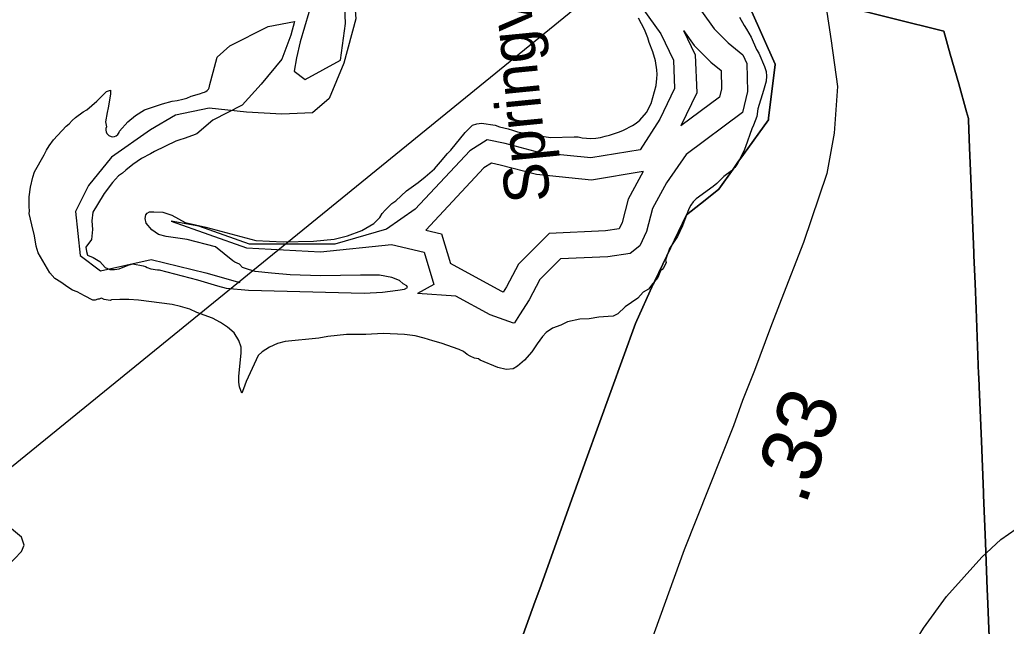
# Model space of a CAD drawing. Extents: x 1662474 to 1856135, y 779280 to 917889.
# Drawn here: x 1715736 to 1717827, y 818196 to 819482 of the extents above; entities that cross this region are included whole.
import ezdxf

# ---------------------------------------------------------------- set-up
doc = ezdxf.new("R2010")
doc.units = 0
for name, color, linetype in [('Exist Boundary Political City Limit New', 7, 'Continuous'), ('Exist Hydrographic Buffer Line', 7, 'Continuous'), ('Exist Hydrographic Creek Single Shore', 7, 'Continuous'), ('Exist Hydrographic Island Shore', 7, 'Continuous'), ('Exist Hydrographic Lake Shore', 7, 'Continuous'), ('Exist Hydrographic Misc Water Feature', 7, 'Continuous'), ('Exist Road Non-System Type 51', 7, 'Continuous'), ('Exist Road Secondary Mileage Tenths English Label', 7, 'Continuous'), ('Exist Road Secondary Structure Standard Bridge Number Label', 7, 'Continuous'), ('Exist Road Secondary Type 51 Attributed', 7, 'Continuous'), ('Exist Road Secondary Type 51 Label', 7, 'Continuous'), ('Map Preparation Boundary City Limit Buffer Line', 7, 'Continuous')]:
    doc.layers.add(name, color=color, linetype=linetype)

msp = doc.modelspace()

# ---------------------------------------------------------------- linework, layer by layer
at = {"layer": 'Exist Boundary Political City Limit New'}
for points in [[(1717284.5, 819505.2), (1717337.2, 819388.2), (1717337.2, 819387.6), (1717323.1, 819273.5), (1717322.6, 819270.2), (1717269.8, 819196.2), (1717258.1, 819179.9), (1717247.6, 819165.2), (1717217.6, 819123), (1717188.5, 819099.9), (1717149, 819068.4)], [(1717149, 819068.4), (1717188.5, 819099.9), (1717217.6, 819123), (1717247.6, 819165.2), (1717258.1, 819179.9), (1717269.8, 819196.2), (1717322.6, 819270.2), (1717323.1, 819273.5), (1717337.2, 819387.6), (1717337.2, 819388.2), (1717284.5, 819505.2)], [(1717790.4, 818173.4), (1717786.9, 818260.4), (1717786.4, 818273.7), (1717782.4, 818373.8), (1717778.4, 818474.2), (1717778.1, 818479.4), (1717773.8, 818588.8), (1717769.2, 818703.4), (1717768.4, 818724.4), (1717768.1, 818730.4), (1717762.6, 818869.1), (1717760.4, 818923), (1717758, 818982.4), (1717757.9, 818987.8), (1717751.5, 819145.7), (1717749, 819210.5), (1717746.6, 819269), (1717746.4, 819273.1), (1717742.5, 819286.9), (1717725.9, 819346), (1717707.9, 819409.6), (1717694.1, 819458.1), (1717478.1, 819512)], [(1717478.1, 819512), (1717694.1, 819458.1), (1717707.9, 819409.6), (1717725.9, 819346), (1717742.5, 819286.9), (1717746.4, 819273.1), (1717746.6, 819269), (1717749, 819210.5), (1717751.5, 819145.7), (1717757.9, 818987.8), (1717758, 818982.4), (1717760.4, 818923), (1717762.6, 818869.1), (1717768.1, 818730.4), (1717768.4, 818724.4), (1717769.2, 818703.4), (1717773.8, 818588.8), (1717778.1, 818479.4), (1717778.4, 818474.2), (1717782.4, 818373.8), (1717786.4, 818273.7), (1717786.9, 818260.4), (1717790.4, 818173.4)], [(1717149, 819068.4), (1717082.1, 818928.8), (1717081.8, 818927.9), (1717080.5, 818925), (1717078.6, 818921.1), (1717040.9, 818837.8), (1716936.5, 818549.8), (1716902.8, 818455.8), (1716869, 818362.1), (1716838, 818275.6), (1716828.5, 818249.1), (1716803, 818178.1)], [(1716803, 818178.1), (1716828.5, 818249.1), (1716838, 818275.6), (1716869, 818362.1), (1716902.8, 818455.8), (1716936.5, 818549.8), (1717040.9, 818837.8), (1717078.6, 818921.1), (1717080.5, 818925), (1717081.8, 818927.9), (1717082.1, 818928.8), (1717149, 819068.4)]]:
    msp.add_lwpolyline(points, dxfattribs=at)
at = {"layer": 'Exist Hydrographic Buffer Line'}
for points in [[(1717039.9, 819528.5), (1717094.3, 819452.3), (1717121.1, 819396.3), (1717123.8, 819336.6), (1717092.5, 819271.7), (1717050.9, 819206.6), (1716945.9, 819189.1), (1716839.2, 819200.2), (1716764.4, 819219.5), (1716726.6, 819227.4), (1716689.8, 819204.4), (1716574.1, 819080.2), (1716513, 819037.9), (1716403.8, 819006), (1716222.6, 819006), (1716115.4, 819044.6), (1716057.1, 819054.8), (1716216.9, 818998.4), (1716373.6, 818990.3), (1716523.5, 819005.9), (1716592.9, 818989.1), (1716613.4, 818920.8), (1716578.8, 818901.6)], [(1717180.8, 819500.4), (1717207.4, 819463.2), (1717237.5, 819433.1), (1717268.2, 819407.8), (1717276.7, 819389.6), (1717278.5, 819330.1), (1717267.8, 819285.7), (1717148.3, 819196.7), (1717106.8, 819136.7), (1717077, 819081.7), (1717064.3, 819033), (1717050.2, 819003.1), (1717029.8, 818986.5), (1716982.3, 818979.7), (1716881.7, 818975.1), (1716838, 818931.3), (1716815.4, 818888.4), (1716795.2, 818856.1), (1716784.8, 818839.2), (1716782.3, 818838.4), (1716733.1, 818856.4), (1716660.3, 818896.1), (1716578.8, 818901.6)], [(1717142.7, 819459.2), (1717165.3, 819427.6), (1717200.4, 819392.4), (1717222.2, 819374.5), (1717223.3, 819335.8), (1717219, 819317.9), (1717137.2, 819257)], [(1717142.7, 819459.2), (1717167.3, 819407.8), (1717170.9, 819327), (1717137.2, 819257)], [(1717057.1, 819160.3), (1716947.4, 819142), (1716830.9, 819154.2), (1716753.9, 819174), (1716735.4, 819177.8), (1716719.8, 819168.1), (1716596.8, 819036.1)], [(1717057.1, 819160.3), (1717025.5, 819102), (1717012.4, 819051.9), (1717006.2, 819038.7), (1716977.1, 819034.5), (1716857.9, 819029), (1716793.2, 818964.2), (1716767.7, 818915.8), (1716760.8, 818904.8), (1716755.9, 818906.6), (1716648.8, 818965)], [(1716596.8, 819036.1), (1716629.9, 819028.1), (1716648.8, 818965)]]:
    msp.add_lwpolyline(points, dxfattribs=at)
at = {"layer": 'Exist Hydrographic Creek Single Shore'}
msp.add_lwpolyline([(1715996.8, 820470.9), (1716158.5, 820299.6), (1716262.1, 820136.1), (1716307.5, 820029.2), (1716378.4, 819865.8), (1716435.4, 819651.8), (1716448.2, 819484.1), (1716422.5, 819389.9), (1716391.5, 819315.4), (1716356.1, 819284.6), (1716291.2, 819281.8), (1716216.8, 819286.5), (1716137.5, 819294.4), (1716066.4, 819279.9), (1716012.8, 819248.9), (1715930.4, 819190.9), (1715881.9, 819130.8), (1715854.2, 819075.8), (1715864, 818982.3), (1715907.5, 818949.8), (1716014.4, 818973.9), (1716130.6, 818945.8), (1716202.2, 818925.1)], dxfattribs=at)
at = {"layer": 'Exist Hydrographic Island Shore'}
msp.add_lwpolyline([(1716340.9, 819355.3), (1716415.7, 819396.7), (1716426.1, 819474.1), (1716420.9, 819618.7), (1716297, 819931.2), (1716263.5, 820075.8), (1716152.5, 820254), (1716054.4, 820334), (1716036.3, 820321.1), (1716033.8, 820274.6), (1716088, 820163.6), (1716134.4, 820055.1), (1716188.6, 819995.8), (1716229.9, 819938.9), (1716281.5, 819848.6), (1716307.3, 819771.1), (1716338.3, 819631.7), (1716348.6, 819497.4), (1716330.6, 819435.4), (1716322.8, 819401.8), (1716317.7, 819373.4)], close=True, dxfattribs=at)
at = {"layer": 'Exist Hydrographic Lake Shore'}
for points in [[(1716127.5, 819328.8), (1716130.6, 819330.1), (1716133.5, 819332.1), (1716135.9, 819335.1), (1716137.5, 819338.2), (1716138.2, 819341.6), (1716138.5, 819345.2), (1716146.2, 819370.8), (1716154.2, 819402.8), (1716180.9, 819426.8), (1716262.2, 819468.1), (1716318.2, 819478.8), (1716310.2, 819449.4), (1716291.6, 819398.8), (1716247.6, 819345.4), (1716207.5, 819301.4), (1716144.9, 819269.4), (1716111, 819240), (1716101.8, 819237.1), (1716084.2, 819230.3), (1716075, 819227.9), (1716066.6, 819224.6), (1716021.8, 819203), (1716012.8, 819197.8), (1715994.1, 819188.1), (1715975.5, 819175.2), (1715960.9, 819163.4), (1715953.5, 819156.8), (1715945.6, 819151.1), (1715932.5, 819137.1), (1715915.1, 819113.8), (1715900.5, 819090.7), (1715890.8, 819073.9), (1715888.9, 819056.1), (1715890.2, 819037.1), (1715888.1, 819015.9), (1715876, 819000.1), (1715877.4, 818990.4), (1715879.5, 818983.3), (1715891.8, 818978.1), (1715906, 818969.4), (1715917.2, 818957.1), (1715926.8, 818952.4), (1715936.6, 818952.4), (1715946.9, 818953.9), (1715965.5, 818961.6), (1715976, 818964.7), (1715997.9, 818960.5), (1716002.2, 818958.9), (1716005.8, 818956.6), (1716014.1, 818953.9), (1716028, 818951.6), (1716031.8, 818951.8), (1716112.8, 818930.8), (1716154.8, 818918), (1716173.4, 818913.2), (1716220.9, 818908.6), (1716465.8, 818902.2), (1716504.9, 818904.3), (1716537.2, 818908.6), (1716551.4, 818911.1), (1716557.4, 818914.3), (1716556.1, 818918), (1716548.8, 818922.2), (1716540.9, 818929), (1716524.4, 818935.6), (1716498.6, 818940.3), (1716458.2, 818940.3), (1716373.4, 818939.2), (1716309.1, 818941.3), (1716269.5, 818944.5), (1716235.1, 818948.2), (1716220.9, 818952.4), (1716207.8, 818957.1), (1716201.8, 818963.9), (1716191.8, 818968.4), (1716187.6, 818971), (1716150.9, 819000.4), (1716090.8, 819015.9), (1716046.6, 819022.2), (1716030.1, 819026.6), (1716016, 819036.9), (1716003.6, 819050.8), (1716001.8, 819060.8), (1716003.1, 819068.6), (1716006, 819072.1), (1716011.2, 819074.9), (1716020.4, 819075.2), (1716039.2, 819073.9), (1716058.5, 819067.6), (1716086.9, 819052.1), (1716130.1, 819042.1), (1716236.6, 819014.1), (1716294.4, 819011.4), (1716358.5, 819012.8), (1716402.2, 819017.2), (1716430.4, 819024), (1716461.1, 819035.6), (1716486.5, 819050), (1716499.1, 819062.6)], [(1716499.1, 819062.6), (1716504.1, 819071.5), (1716510.1, 819078.6), (1716524.6, 819092.2), (1716533.2, 819098.3), (1716555.6, 819119.3), (1716580.2, 819136.9), (1716595.2, 819149.2), (1716614.6, 819166.2), (1716627.8, 819180.7), (1716642.8, 819198.8), (1716649.8, 819205.6), (1716680, 819242.9), (1716695.5, 819258.9), (1716704.9, 819261.8), (1716714.4, 819262.9), (1716743.8, 819258.6), (1716752.6, 819255.2), (1716770.8, 819250.8), (1716780.5, 819248.2), (1716791, 819244.2), (1716811.8, 819240), (1716861.1, 819232.7), (1716910.6, 819234.2), (1716919.6, 819233.8), (1716928.2, 819231.9), (1716945.9, 819230.3), (1716957.1, 819231.1), (1716966.6, 819232.7), (1716976.9, 819235.6), (1716985.5, 819237.4), (1717007, 819244.5), (1717015.6, 819248.4), (1717034.2, 819258.1), (1717042.1, 819263.1), (1717049.8, 819269.1), (1717064.2, 819285.7), (1717073.9, 819304.9), (1717084.4, 819342.9), (1717086.2, 819357.6), (1717086.8, 819366.2), (1717086.2, 819375.7), (1717083.6, 819395.4), (1717077.6, 819414.1), (1717070.2, 819434.2), (1717067.1, 819444.2), (1717060.2, 819461.8), (1717047.1, 819485.7)], [(1717261.6, 819487.8), (1717271, 819470.2), (1717276.2, 819462.6), (1717286, 819445.2), (1717297, 819419.3), (1717302, 819411.1), (1717314.6, 819382.8), (1717317.5, 819372.3), (1717318.8, 819362.9), (1717317.8, 819352.1), (1717312.5, 819332.4), (1717300.5, 819293.1), (1717297.9, 819277), (1717291.2, 819258.6), (1717287.6, 819250.8), (1717274.2, 819212.8), (1717270.2, 819203.2), (1717256.9, 819177.6), (1717251.4, 819168.9), (1717244, 819161.6), (1717228, 819149.5), (1717213, 819134.8), (1717205.8, 819128.5), (1717169.8, 819102.2), (1717163.4, 819096.2), (1717157.9, 819088.8), (1717153.8, 819081.2), (1717140.4, 819045.2), (1717130.1, 819022.2), (1717113.2, 818997), (1717104.6, 818972.6), (1717105.8, 818967.6), (1717100.8, 818956.6), (1717097.5, 818952.4), (1717093.6, 818950), (1717087.9, 818935.6), (1717077.6, 818922.9), (1717068.4, 818911.1), (1717056.9, 818904.3), (1717045.6, 818892), (1717019.1, 818873.1), (1717003.4, 818858.4), (1716993.6, 818853.9), (1716983.1, 818852.9), (1716962.9, 818851.8), (1716942.5, 818848.2), (1716923, 818846.9), (1716896.8, 818841.3), (1716882.6, 818834.5), (1716864.8, 818828.2), (1716851.9, 818819.1), (1716844, 818810.1), (1716832.8, 818794.6), (1716821.1, 818777.6), (1716806, 818760.5), (1716791, 818747.4), (1716781.5, 818741.9), (1716766.6, 818740.8), (1716749.5, 818745), (1716711.8, 818760.5), (1716708.1, 818762.9), (1716699.9, 818764.7), (1716690.2, 818768.6), (1716684.5, 818772.1), (1716676.6, 818778.6), (1716667.1, 818783.1), (1716628.8, 818796.4), (1716611.2, 818801.2), (1716592.9, 818806.9), (1716574.2, 818811.9), (1716551.4, 818814.8)], [(1716551.4, 818814.8), (1716506.5, 818816.7), (1716469.5, 818814.8), (1716428.8, 818814.8), (1716389.1, 818810.1), (1716369.8, 818806.9), (1716298.6, 818800.1), (1716282.1, 818795.4), (1716265.2, 818787.8), (1716250.1, 818777.6), (1716241.1, 818769.9), (1716215.6, 818714.8), (1716210.4, 818699.1), (1716206.8, 818690.4), (1716201.8, 818703.8), (1716200.5, 818713.8), (1716200.5, 818726.1), (1716205.5, 818775.4), (1716205.5, 818787.8), (1716200.5, 818802.2), (1716190.5, 818818), (1716176, 818830.3), (1716161.1, 818840.3), (1716144.5, 818849.2), (1716111, 818861.6), (1716096.8, 818868.4), (1716076.6, 818874.1), (1716059, 818878.1), (1715987.6, 818887.8), (1715967.4, 818888.6), (1715948.2, 818888.6), (1715930.6, 818888.1), (1715927.5, 818887), (1715915.1, 818888.9), (1715910.8, 818891.2), (1715908.4, 818891.5), (1715904.6, 818889.4), (1715901.2, 818889.9), (1715895.8, 818887.8), (1715890.8, 818887.8), (1715872.9, 818896.4), (1715857.4, 818905.1), (1715847.5, 818908.6), (1715838.2, 818915.1), (1715823, 818925.9), (1715810.5, 818933.4), (1715800, 818945.6), (1715774.8, 818988.1), (1715771.1, 819001.9), (1715767.4, 819023.8), (1715761.6, 819047.4), (1715756.1, 819071.5), (1715756.9, 819076.2), (1715756.1, 819086.5), (1715755.9, 819106.7), (1715759, 819127.4), (1715763.5, 819148.7), (1715767.6, 819160), (1715787.9, 819195.7), (1715792.4, 819205.6), (1715798.4, 819215.1), (1715807.2, 819227.7), (1715834.4, 819256.8), (1715840.6, 819261.8), (1715846.9, 819268.4), (1715854.2, 819274.7), (1715870.2, 819287), (1715878.4, 819291.2), (1715899.1, 819309.6), (1715919.6, 819329.8), (1715928, 819332.9), (1715928.5, 819324.2), (1715923.2, 819295.4), (1715921, 819285.7), (1715918, 819266), (1715919.6, 819255.2), (1715918.4, 819251.8), (1715918.4, 819248.2), (1715918.9, 819244.8), (1715920.4, 819241.3), (1715924.6, 819237.1), (1715929.9, 819234.8), (1715933.5, 819234.2), (1715937, 819234.8), (1715940.4, 819236.4), (1715944, 819239.2), (1715946.6, 819243.2), (1715947.5, 819246.3), (1715964.8, 819266), (1715981.2, 819278.9), (1716000.5, 819290.9), (1716038.2, 819304.1), (1716059.2, 819309.8), (1716069.5, 819311.1), (1716081.6, 819313.8), (1716090.2, 819316.1), (1716099.4, 819320.1), (1716117.2, 819325.3), (1716124.9, 819328.2), (1716127.5, 819328.8)]]:
    msp.add_lwpolyline(points, dxfattribs=at)
at = {"layer": 'Exist Hydrographic Misc Water Feature'}
msp.add_lwpolyline([(1717315.2, 817768.6), (1717339.3, 817782.3), (1717371.6, 817814), (1717408, 817851.7), (1717484.9, 817939), (1717561.7, 818034.3), (1717590.2, 818084.1), (1717614.7, 818131.8), (1717651.2, 818191.5), (1717700, 818259.1), (1717774.7, 818342.4), (1717815.1, 818380), (1717863.5, 818413.6), (1717901.7, 818437.2), (1717998.2, 818492.4), (1718058.5, 818523.8), (1718195.1, 818574.5), (1718259.4, 818597.9), (1718317.4, 818601.3), (1718363.2, 818588.9)], dxfattribs=at)
at = {"layer": 'Exist Road Non-System Type 51'}
msp.add_lwpolyline([(1715694.9, 818307.5), (1715739.9, 818354.2), (1715745.1, 818367.9), (1715739.4, 818384.9), (1715697.4, 818420.4)], dxfattribs=at)
at = {"layer": 'Exist Road Secondary Structure Standard Bridge Number Label'}
msp.add_line((1717360.4, 819870.9), (1715707.3, 818524.3), dxfattribs=at)
at = {"layer": 'Exist Road Secondary Type 51 Attributed'}
msp.add_lwpolyline([(1717466.6, 820103.1), (1717453.7, 820038.2), (1717443.5, 819973.8), (1717433, 819924.1), (1717422.5, 819866.6), (1717421.2, 819811.5), (1717414.3, 819770.2), (1717423.6, 819626.2), (1717444.2, 819512.6), (1717455.4, 819437.4), (1717468.9, 819340.6), (1717462.2, 819241.5), (1717446.4, 819155.9), (1717396.8, 819009.5), (1717349.5, 818887.9), (1717326.9, 818829.3), (1717293.1, 818738), (1717267.8, 818674.7), (1717248.8, 818620.9), (1717144.3, 818358.3), (1717071.5, 818156.6)], dxfattribs=at)
at = {"layer": 'Map Preparation Boundary City Limit Buffer Line'}
for points in [[(1717284.5, 819505.2), (1717337.2, 819388.2), (1717337.2, 819387.6), (1717323.1, 819273.5), (1717322.6, 819270.2), (1717269.8, 819196.2), (1717258.1, 819179.9), (1717247.6, 819165.2), (1717217.6, 819123), (1717188.5, 819099.9), (1717149, 819068.4)], [(1717149, 819068.4), (1717188.5, 819099.9), (1717217.6, 819123), (1717247.6, 819165.2), (1717258.1, 819179.9), (1717269.8, 819196.2), (1717322.6, 819270.2), (1717323.1, 819273.5), (1717337.2, 819387.6), (1717337.2, 819388.2), (1717284.5, 819505.2)], [(1717790.4, 818173.4), (1717786.9, 818260.4), (1717786.4, 818273.7), (1717782.4, 818373.8), (1717778.4, 818474.2), (1717778.1, 818479.4), (1717773.8, 818588.8), (1717769.2, 818703.4), (1717768.4, 818724.4), (1717768.1, 818730.4), (1717762.6, 818869.1), (1717760.4, 818923), (1717758, 818982.4), (1717757.9, 818987.8), (1717751.5, 819145.7), (1717749, 819210.5), (1717746.6, 819269), (1717746.4, 819273.1), (1717742.5, 819286.9), (1717725.9, 819346), (1717707.9, 819409.6), (1717694.1, 819458.1), (1717478.1, 819512)], [(1717478.1, 819512), (1717694.1, 819458.1), (1717707.9, 819409.6), (1717725.9, 819346), (1717742.5, 819286.9), (1717746.4, 819273.1), (1717746.6, 819269), (1717749, 819210.5), (1717751.5, 819145.7), (1717757.9, 818987.8), (1717758, 818982.4), (1717760.4, 818923), (1717762.6, 818869.1), (1717768.1, 818730.4), (1717768.4, 818724.4), (1717769.2, 818703.4), (1717773.8, 818588.8), (1717778.1, 818479.4), (1717778.4, 818474.2), (1717782.4, 818373.8), (1717786.4, 818273.7), (1717786.9, 818260.4), (1717790.4, 818173.4)], [(1717149, 819068.4), (1717082.1, 818928.8), (1717081.8, 818927.9), (1717080.5, 818925), (1717078.6, 818921.1), (1717040.9, 818837.8), (1716936.5, 818549.8), (1716902.8, 818455.8), (1716869, 818362.1), (1716838, 818275.6), (1716828.5, 818249.1), (1716803, 818178.1)], [(1716803, 818178.1), (1716828.5, 818249.1), (1716838, 818275.6), (1716869, 818362.1), (1716902.8, 818455.8), (1716936.5, 818549.8), (1717040.9, 818837.8), (1717078.6, 818921.1), (1717080.5, 818925), (1717081.8, 818927.9), (1717082.1, 818928.8), (1717149, 819068.4)]]:
    msp.add_lwpolyline(points, dxfattribs=at)

# ---------------------------------------------------------------- texts
at = {"layer": 'Exist Road Secondary Mileage Tenths English Label'}
msp.add_text('.33', height=125, rotation=70.7377, dxfattribs=at).set_placement((1717400.9, 818450.1))
at = {"layer": 'Exist Road Secondary Type 51 Label'}
msp.add_text('Springview Dr', height=95, rotation=95.6268, dxfattribs=at).set_placement((1716860.7, 819098.6))

doc.saveas('drawing.dxf')
